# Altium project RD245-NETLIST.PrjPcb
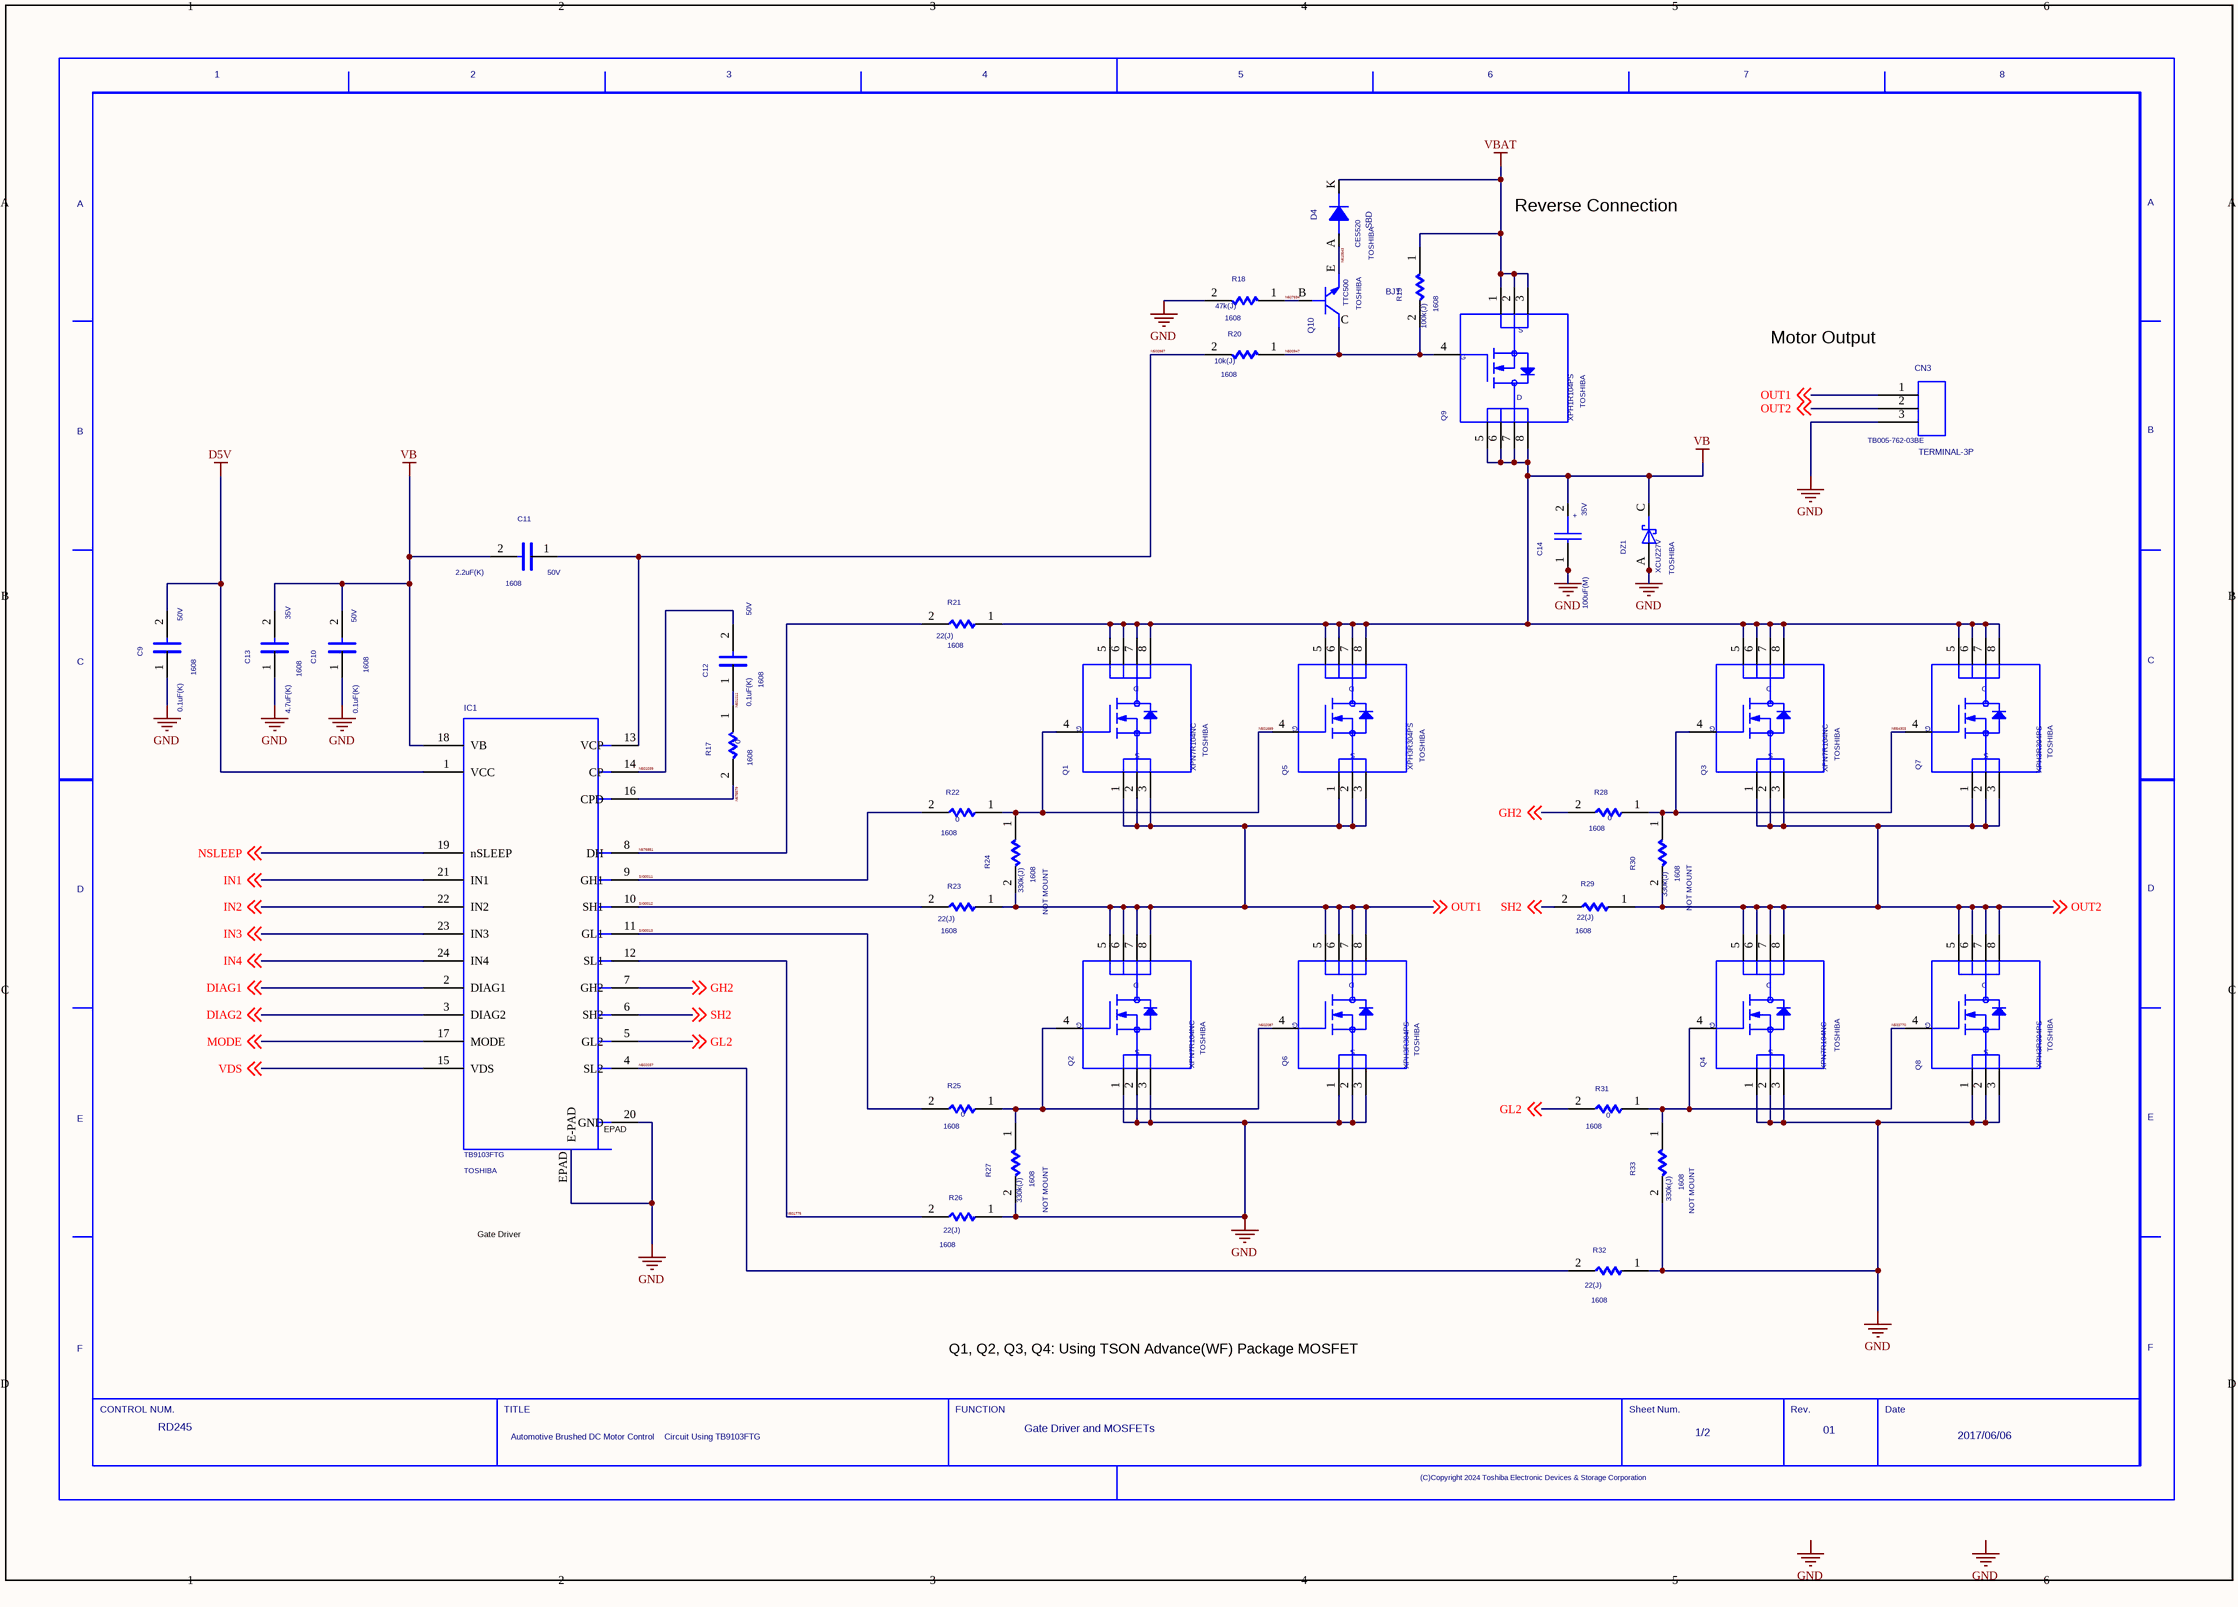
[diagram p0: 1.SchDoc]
2 sheets, 97 parts. Net scope: global (net labels, ports and power ports of the same name join across sheets).
Sheets:
  1.SchDoc
  2.SchDoc

## Sheet 1.SchDoc
size 420 x 297 mm

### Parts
(Parts that share a designator on the sheet are numbered #1, #2 ... from top to bottom, then left to right.)
C9  SIZECODESMD: 1608  VAL2: 50V  VAL1: 0.1uF(K)  (hidden comment: C)
C10  SIZECODESMD: 1608  VAL2: 50V  VAL1: 0.1uF(K)  (hidden comment: C)
C11  SIZECODESMD: 1608  VAL2: 50V  VAL1: 2.2uF(K)  (hidden comment: C)
C12  SIZECODESMD: 1608  VAL2: 50V  VAL1: 0.1uF(K)  (hidden comment: C)
C13  SIZECODESMD: 1608  VAL2: 35V  VAL1: 4.7uF(K)  (hidden comment: C)
C14  VAL2: 35V  VAL1: 100uF(M)  (hidden comment: CP)
CN3  TERMINAL-3P  VAL3: TB005-762-03BE
D4  SBD  USERCOMPTEXT3: TOSHIBA  VAL3: CES520
DZ1  VAL3: XCUZ27V  USERCOMPTEXT3: TOSHIBA  (hidden comment: SBD)
IC1  USERCOMPTEXT3: TOSHIBA  VAL3: TB9103FTG  (hidden comment: TC241_3)
Q1  VAL3: XPN7R104NC  USERCOMPTEXT3: TOSHIBA  (hidden comment: MFNAC)
Q2  VAL3: XPN7R104NC  USERCOMPTEXT3: TOSHIBA  (hidden comment: MFNAC)
Q3  VAL3: XPN7R104NC  USERCOMPTEXT3: TOSHIBA  (hidden comment: MFNAC)
Q4  VAL3: XPN7R104NC  USERCOMPTEXT3: TOSHIBA  (hidden comment: MFNAC)
Q5  VAL3: XPH3R304PS  USERCOMPTEXT3: TOSHIBA  (hidden comment: MFNAC)
Q6  VAL3: XPH3R304PS  USERCOMPTEXT3: TOSHIBA  (hidden comment: MFNAC)
Q7  VAL3: XPH3R304PS  USERCOMPTEXT3: TOSHIBA  (hidden comment: MFNAC)
Q8  VAL3: XPH3R304PS  USERCOMPTEXT3: TOSHIBA  (hidden comment: MFNAC)
Q9  VAL3: XPH1R104PS  USERCOMPTEXT3: TOSHIBA  (hidden comment: MFNAC)
Q10  BJT  USERCOMPTEXT3: TOSHIBA  VAL3: TTC500
R17  SIZECODESMD: 1608  VAL1: 0  (hidden comment: R)
R18  SIZECODESMD: 1608  VAL1: 47k(J)  (hidden comment: R)
R19  SIZECODESMD: 1608  VAL1: 100k(J)  (hidden comment: R)
R20  SIZECODESMD: 1608  VAL1: 10k(J)  (hidden comment: R)
R21  SIZECODESMD: 1608  VAL1: 22(J)  (hidden comment: R)
R22  SIZECODESMD: 1608  VAL1: 0  (hidden comment: R)
R23  SIZECODESMD: 1608  VAL1: 22(J)  (hidden comment: R)
R24  SIZECODESMD: 1608  VAL1: 330k(J)  NOTMOUNT: NOT MOUNT  (hidden comment: R)
R25  SIZECODESMD: 1608  VAL1: 0  (hidden comment: R)
R26  SIZECODESMD: 1608  VAL1: 22(J)  (hidden comment: R)
R27  SIZECODESMD: 1608  VAL1: 330k(J)  NOTMOUNT: NOT MOUNT  (hidden comment: R)
R28  SIZECODESMD: 1608  VAL1: 0  (hidden comment: R)
R29  SIZECODESMD: 1608  VAL1: 22(J)  (hidden comment: R)
R30  SIZECODESMD: 1608  VAL1: 330k(J)  NOTMOUNT: NOT MOUNT  (hidden comment: R)
R31  SIZECODESMD: 1608  VAL1: 0  (hidden comment: R)
R32  SIZECODESMD: 1608  VAL1: 22(J)  (hidden comment: R)
R33  SIZECODESMD: 1608  VAL1: 330k(J)  NOTMOUNT: NOT MOUNT  (hidden comment: R)
U?#1  DATE: 2017/06/06  REVISION: 01  FUNCTION: Gate Driver and MOSFETs  DRAWINGNUMBER: RD245  TITLE: Automotive Brushed DC Motor Control / Circuit Using TB9103FTG  SHEETNUMBER: 1/2  (hidden comment: WAKU_DEF100)

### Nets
D5V: C9.2 IC1.1(VCC)
GND: C9.1 C10.1 C13.1 C14.1 CN3.3 DZ1.A IC1.20(GND) IC1.EPAD(E-PAD) Q2.1 Q2.2 Q2.3 Q4.1 Q4.2 Q4.3 Q6.1 Q6.2 Q6.3 Q8.1 Q8.2 Q8.3 R18.2 R26.1 R27.2 R32.1 R33.2
VB: C10.2 C11.2 C13.2 C14.2 DZ1.C IC1.18(VB) Q1.5 Q1.6 Q1.7 Q1.8 Q3.5 Q3.6 Q3.7 Q3.8 Q5.5 Q5.6 Q5.7 Q5.8 Q7.5 Q7.6 Q7.7 Q7.8 Q9.5 Q9.6 Q9.7 Q9.8 R21.1
VBAT: D4.K Q9.1 Q9.2 Q9.3 R19.1
DIAG1: IC1.2(DIAG1) ; off-sheet DIAG1
DIAG2: IC1.3(DIAG2) ; off-sheet DIAG2
GH2: IC1.7(GH2) R28.2 ; off-sheet GH2
GL2: IC1.5(GL2) R31.2 ; off-sheet GL2
IN1: IC1.21(IN1) ; off-sheet IN1
IN2: IC1.22(IN2) ; off-sheet IN2
IN3: IC1.23(IN3) ; off-sheet IN3
IN4: IC1.24(IN4) ; off-sheet IN4
MODE: IC1.17(MODE) ; off-sheet MODE
N500947: Q9.4 Q10.C R19.2 R20.1
N500987: C11.1 IC1.13(VCP) R20.2
N501039: C12.2 IC1.14(CP)
N501211: C12.1 R17.1
N501689: Q1.4 Q5.4 R22.1 R24.1
N501775: IC1.12(SL1) R26.2
N502037: IC1.4(SL2) R32.2
N502087: Q2.4 Q6.4 R25.1 R27.1
N533770: Q4.4 Q8.4 R31.1 R33.1
N554303: Q3.4 Q7.4 R28.1 R30.1
N575579: IC1.16(CPD) R17.2
N576851: IC1.8(DH) R21.2
N607694: Q10.B R18.1
N610543: D4.A Q10.E
NSLEEP: IC1.19(nSLEEP) ; off-sheet NSLEEP
OUT1: CN3.1 Q1.1 Q1.2 Q1.3 Q2.5 Q2.6 Q2.7 Q2.8 Q5.1 Q5.2 Q5.3 Q6.5 Q6.6 Q6.7 Q6.8 R23.1 R24.2 ; off-sheet OUT1
OUT2: CN3.2 Q3.1 Q3.2 Q3.3 Q4.5 Q4.6 Q4.7 Q4.8 Q7.1 Q7.2 Q7.3 Q8.5 Q8.6 Q8.7 Q8.8 R29.1 R30.2 ; off-sheet OUT2
SH2: IC1.6(SH2) R29.2 ; off-sheet SH2
SIG0011: IC1.9(GH1) R22.2
SIG0012: IC1.10(SH1) R23.2
SIG0013: IC1.11(GL1) R25.2
VDS: IC1.15(VDS) ; off-sheet VDS

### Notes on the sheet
- Reverse Connection
  Protector
- Motor Output
- (near IC1) EPAD
- Gate Driver
- Q1, Q2, Q3, Q4: Using TSON Advance(WF) Package MOSFET
  Q5, Q6, Q7, Q8: Using SOP Advance(WF) Package MOSFET
- Labels drawn without touching a wire or pin: GND

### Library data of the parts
C9 = C: UPDATETIME: 17:22:43; UPDATEUSER: sptcae13; SAVECOUNT: 1; ORIGINALSYMBOLORIGIN: (0,0); QUADMODEL: CON_10U; FUNCN: C_C; NOMINALCAPACITA: 10u; RATEDVOLTAGE: 25; CDMASTERCADCELG: KC0167; MAKER: TDK; OUMEMAKER: MRT 村田製作所; ADSMODELNAME: s_ZRB18AR61E106ME01L; VAL4: Murata; FNLEADFREETHET1GT2GMCTH1: N_N_N; VAL3: GCM188R71H104KA57J; CAPACITANCETOLE: M; OUMECLASSIFICATION: セラミックコンデンサ; OUMEMAKERKATAMEI: ZRB18AR61E106ME01L; INSTANCENAME: INS530329
C10 = C: UPDATETIME: 17:22:43; UPDATEUSER: sptcae13; SAVECOUNT: 1; ORIGINALSYMBOLORIGIN: (0,0); QUADMODEL: CON_10U; FUNCN: C_C; NOMINALCAPACITA: 10u; RATEDVOLTAGE: 25; CDMASTERCADCELG: KC0167; MAKER: TDK; OUMEMAKER: MRT 村田製作所; ADSMODELNAME: s_ZRB18AR61E106ME01L; VAL4: Murata; FNLEADFREETHET1GT2GMCTH1: N_N_N; VAL3: GCM188R71H104KA57J; CAPACITANCETOLE: M; OUMECLASSIFICATION: セラミックコンデンサ; OUMEMAKERKATAMEI: ZRB18AR61E106ME01L; INSTANCENAME: INS530425
C11 = C: UPDATETIME: 17:22:43; UPDATEUSER: sptcae13; SAVECOUNT: 1; ORIGINALSYMBOLORIGIN: (0,0); QUADMODEL: CON_10U; FUNCN: C_C; NOMINALCAPACITA: 10u; RATEDVOLTAGE: 25; CDMASTERCADCELG: KC0167; MAKER: TDK; OUMEMAKER: MRT 村田製作所; ADSMODELNAME: s_ZRB18AR61E106ME01L; VAL4: Murata; FNLEADFREETHET1GT2GMCTH1: N_N_N; VAL3: GRT188R61H225KE13D; CAPACITANCETOLE: M; OUMECLASSIFICATION: セラミックコンデンサ; OUMEMAKERKATAMEI: ZRB18AR61E106ME01L; INSTANCENAME: INS530173
C12 = C: UPDATETIME: 17:22:43; UPDATEUSER: sptcae13; SAVECOUNT: 1; ORIGINALSYMBOLORIGIN: (0,0); QUADMODEL: CON_10U; FUNCN: C_C; NOMINALCAPACITA: 10u; RATEDVOLTAGE: 25; CDMASTERCADCELG: KC0167; MAKER: TDK; OUMEMAKER: MRT 村田製作所; ADSMODELNAME: s_ZRB18AR61E106ME01L; VAL4: Murata; FNLEADFREETHET1GT2GMCTH1: N_N_N; VAL3: GCM188R71H104KA57J; CAPACITANCETOLE: M; OUMECLASSIFICATION: セラミックコンデンサ; OUMEMAKERKATAMEI: ZRB18AR61E106ME01L; INSTANCENAME: INS529943
C13 = C: UPDATETIME: 17:22:43; UPDATEUSER: sptcae13; SAVECOUNT: 1; ORIGINALSYMBOLORIGIN: (0,0); QUADMODEL: CON_10U; FUNCN: C_C; NOMINALCAPACITA: 10u; RATEDVOLTAGE: 25; CDMASTERCADCELG: KC0167; MAKER: TDK; OUMEMAKER: MRT 村田製作所; ADSMODELNAME: s_ZRB18AR61E106ME01L; VAL4: Murata; FNLEADFREETHET1GT2GMCTH1: N_N_N; VAL3: GRT188R6YA475KE13D; CAPACITANCETOLE: M; OUMECLASSIFICATION: セラミックコンデンサ; OUMEMAKERKATAMEI: ZRB18AR61E106ME01L; INSTANCENAME: INS647841
C14 = CP: OUMEPARTTYPE: C; SAVEAREA0: -1450,-153,20294,13055; UPDATETIME: 16:13:42; UPDATEUSER: fukuda-y; TIME: 15:02:55; SAVECOUNT: 52; ORIGINALSYMBOLORIGIN: (0,0); QUADMODEL: CON_330U; FUNCN: CP_CP; RATEDVOLTAGE: 450; NOMINALCAPACITA: 330u; CDMASTERCADCELG: DC213N; MAKER: RUBYCON; GCOUNT: 1; SIZECODESMD: DIP; OUMEMAKER: SIT ルビコン; VAL4: Chemi-Con; FNLEADFREETHET1GT2GMCTH1: 9_N_N; VAL3: HHXD350ARA101MHA0G; CAPACITANCETOLE: M; OUMECLASSIFICATION: アルミ電解コンデンサ; OUMEMAKERKATAMEI: 450MXC330M35X40; CHIPSIZE: D35xL30; INSTANCENAME: INS636800
CN3 = CON3: SAVECOUNT: 1; UPDATEUSER: sptcae13; UPDATETIME: 09:49:24; OriginalSymbolOrigin: (0,0); FUNCN: CON3_CON3; VAL4: CUI Devices; VAL2: 300V/30A; INSTANCENAME: INS530345
D4 = DIODE_0: SAVECOUNT: 1; UPDATEUSER: sptcae13; UPDATETIME: 09:49:24; OriginalSymbolOrigin: (0,0); FUNCN: DIODE_0_DIODE_0; INSTANCENAME: INS530245
DZ1 = SBD: SAVEAREA0: -4630,-153,17114,13055; UPDATETIME: 08:16:22; UPDATEUSER: fukuda-y; TIME: 14:49:55; SAVECOUNT: 1; ORIGINALSYMBOLORIGIN: (0,0); COMPONENTNAME: SBD_SBD; INSTANCENAME: INS530189
IC1 = TC241_3: SAVECOUNT: 1; UPDATEUSER: sptcae13; UPDATETIME: 09:49:24; OriginalSymbolOrigin: (0,0); FUNCN: TC241_3_Graphic_Schematic_1_package; VAL1: GATE_DRIVER; INSTANCENAME: cmp65
Q1 = MFNAC_23: SAVEAREA0: -10143,-336,37609,28718; UPDATETIME: 14:45:16; UPDATEUSER: 19990028; TIME: 18:29:30; SAVECOUNT: 1; ORIGINALSYMBOLORIGIN: (0,0); COMPONENTNAME: MFNAC_23_MFNAC_23; INSTANCENAME: INS529903
Q2 = MFNAC_23: SAVEAREA0: -10143,-336,37609,28718; UPDATETIME: 14:45:16; UPDATEUSER: 19990028; TIME: 18:29:30; SAVECOUNT: 1; ORIGINALSYMBOLORIGIN: (0,0); COMPONENTNAME: MFNAC_23_MFNAC_23; INSTANCENAME: INS530205
Q3 = MFNAC_23: SAVEAREA0: -10143,-336,37609,28718; UPDATETIME: 14:45:16; UPDATEUSER: 19990028; TIME: 18:29:30; SAVECOUNT: 1; ORIGINALSYMBOLORIGIN: (0,0); COMPONENTNAME: MFNAC_23_MFNAC_23; INSTANCENAME: INS533486
Q4 = MFNAC_23: SAVEAREA0: -10143,-336,37609,28718; UPDATETIME: 14:45:16; UPDATEUSER: 19990028; TIME: 18:29:30; SAVECOUNT: 1; ORIGINALSYMBOLORIGIN: (0,0); COMPONENTNAME: MFNAC_23_MFNAC_23; INSTANCENAME: INS533696
Q5 = MFNAC_23: SAVEAREA0: -10143,-336,37609,28718; UPDATETIME: 14:45:16; UPDATEUSER: 19990028; TIME: 18:29:30; SAVECOUNT: 1; ORIGINALSYMBOLORIGIN: (0,0); COMPONENTNAME: MFNAC_23_MFNAC_23; INSTANCENAME: INS530025
Q6 = MFNAC_23: SAVEAREA0: -10143,-336,37609,28718; UPDATETIME: 14:45:16; UPDATEUSER: 19990028; TIME: 18:29:30; SAVECOUNT: 1; ORIGINALSYMBOLORIGIN: (0,0); COMPONENTNAME: MFNAC_23_MFNAC_23; INSTANCENAME: INS530385
Q7 = MFNAC_23: SAVEAREA0: -10143,-336,37609,28718; UPDATETIME: 14:45:16; UPDATEUSER: 19990028; TIME: 18:29:30; SAVECOUNT: 1; ORIGINALSYMBOLORIGIN: (0,0); COMPONENTNAME: MFNAC_23_MFNAC_23; INSTANCENAME: INS533510
Q8 = MFNAC_23: SAVEAREA0: -10143,-336,37609,28718; UPDATETIME: 14:45:16; UPDATEUSER: 19990028; TIME: 18:29:30; SAVECOUNT: 1; ORIGINALSYMBOLORIGIN: (0,0); COMPONENTNAME: MFNAC_23_MFNAC_23; INSTANCENAME: INS533720
Q9 = MFNAC_23: SAVEAREA0: -10143,-336,37609,28718; UPDATETIME: 14:45:16; UPDATEUSER: 19990028; TIME: 18:29:30; SAVECOUNT: 1; ORIGINALSYMBOLORIGIN: (0,0); COMPONENTNAME: MFNAC_23_MFNAC_23; INSTANCENAME: INS529983
Q10 = 2N1069_0: SAVECOUNT: 1; UPDATEUSER: sptcae13; UPDATETIME: 09:49:24; PSPICETEMPLATE: Q^@REFDES %C %B %E; OriginalSymbolOrigin: (0,5080); FUNCN: 2N1069_0_2N1069_0; INSTANCENAME: INS529959
R17 = R: UPDATETIME: 17:22:43; UPDATEUSER: sptcae13; SAVECOUNT: 1; ORIGINALSYMBOLORIGIN: (0,0); QUADMODEL: RES_1M; FUNCN: R_R; CDMASTERCADCELG: KC0020; MAKER: KOA; RESISTANCETOLER: J; OUMEMAKER: SSM 進工業; POWERRATING: 500m; MOUNTINGFORMSMD: SMD; NOMINALRESISTAN: 1m; ADSMODELNAME: s_RL1632H_R001_JN; FNLEADFREETHET1GT2GMCTH1: N_N_N; VAL3: RK73Z1JTTD; OUMECLASSIFICATION: 表面実装用固定抵抗器; OUMEMAKERKATAMEI: RL1632H-R001-JN; CHIPSIZE: 3216; INSTANCENAME: INS529855
R18 = R: UPDATETIME: 17:22:43; UPDATEUSER: sptcae13; SAVECOUNT: 1; ORIGINALSYMBOLORIGIN: (0,0); QUADMODEL: RES_1M; FUNCN: R_R; CDMASTERCADCELG: KC0020; MAKER: KOA; RESISTANCETOLER: J; OUMEMAKER: SSM 進工業; POWERRATING: 500m; MOUNTINGFORMSMD: SMD; NOMINALRESISTAN: 1m; ADSMODELNAME: s_RL1632H_R001_JN; FNLEADFREETHET1GT2GMCTH1: N_N_N; VAL3: RK73B1JTTD473J; VAL2: 100mW; OUMECLASSIFICATION: 表面実装用固定抵抗器; OUMEMAKERKATAMEI: RL1632H-R001-JN; CHIPSIZE: 3216; INSTANCENAME: INS529871
R19 = R: UPDATETIME: 17:22:43; UPDATEUSER: sptcae13; SAVECOUNT: 1; ORIGINALSYMBOLORIGIN: (0,0); QUADMODEL: RES_1M; FUNCN: R_R; CDMASTERCADCELG: KC0020; MAKER: KOA; RESISTANCETOLER: J; OUMEMAKER: SSM 進工業; POWERRATING: 500m; MOUNTINGFORMSMD: SMD; NOMINALRESISTAN: 1m; ADSMODELNAME: s_RL1632H_R001_JN; FNLEADFREETHET1GT2GMCTH1: N_N_N; VAL3: RK73B1JTTD104J; VAL2: 100mW; OUMECLASSIFICATION: 表面実装用固定抵抗器; OUMEMAKERKATAMEI: RL1632H-R001-JN; CHIPSIZE: 3216; INSTANCENAME: INS530265
R20 = R: UPDATETIME: 17:22:43; UPDATEUSER: sptcae13; SAVECOUNT: 1; ORIGINALSYMBOLORIGIN: (0,0); QUADMODEL: RES_1M; FUNCN: R_R; CDMASTERCADCELG: KC0020; MAKER: KOA; RESISTANCETOLER: J; OUMEMAKER: SSM 進工業; POWERRATING: 500m; MOUNTINGFORMSMD: SMD; NOMINALRESISTAN: 1m; ADSMODELNAME: s_RL1632H_R001_JN; FNLEADFREETHET1GT2GMCTH1: N_N_N; VAL3: RK73B1JTTD103J; VAL2: 100mW; OUMECLASSIFICATION: 表面実装用固定抵抗器; OUMEMAKERKATAMEI: RL1632H-R001-JN; CHIPSIZE: 3216; INSTANCENAME: INS529887
R21 = R: UPDATETIME: 17:22:43; UPDATEUSER: sptcae13; SAVECOUNT: 1; ORIGINALSYMBOLORIGIN: (0,0); QUADMODEL: RES_1M; FUNCN: R_R; CDMASTERCADCELG: KC0020; MAKER: KOA; RESISTANCETOLER: J; OUMEMAKER: SSM 進工業; POWERRATING: 500m; MOUNTINGFORMSMD: SMD; NOMINALRESISTAN: 1m; ADSMODELNAME: s_RL1632H_R001_JN; FNLEADFREETHET1GT2GMCTH1: N_N_N; VAL3: RK73B1JTTD220J; VAL2: 125mW; OUMECLASSIFICATION: 表面実装用固定抵抗器; OUMEMAKERKATAMEI: RL1632H-R001-JN; CHIPSIZE: 3216; INSTANCENAME: INS575614
R22 = R: UPDATETIME: 17:22:43; UPDATEUSER: sptcae13; SAVECOUNT: 1; ORIGINALSYMBOLORIGIN: (0,0); QUADMODEL: RES_1M; FUNCN: R_R; CDMASTERCADCELG: KC0020; MAKER: KOA; RESISTANCETOLER: J; OUMEMAKER: SSM 進工業; POWERRATING: 500m; MOUNTINGFORMSMD: SMD; NOMINALRESISTAN: 1m; ADSMODELNAME: s_RL1632H_R001_JN; FNLEADFREETHET1GT2GMCTH1: N_N_N; VAL3: RK73Z1JTTD; OUMECLASSIFICATION: 表面実装用固定抵抗器; OUMEMAKERKATAMEI: RL1632H-R001-JN; CHIPSIZE: 3216; INSTANCENAME: INS530281
R23 = R: UPDATETIME: 17:22:43; UPDATEUSER: sptcae13; SAVECOUNT: 1; ORIGINALSYMBOLORIGIN: (0,0); QUADMODEL: RES_1M; FUNCN: R_R; CDMASTERCADCELG: KC0020; MAKER: KOA; RESISTANCETOLER: J; OUMEMAKER: SSM 進工業; POWERRATING: 500m; MOUNTINGFORMSMD: SMD; NOMINALRESISTAN: 1m; ADSMODELNAME: s_RL1632H_R001_JN; FNLEADFREETHET1GT2GMCTH1: N_N_N; VAL3: RK73B1JTTD220J; VAL2: 125mW; OUMECLASSIFICATION: 表面実装用固定抵抗器; OUMEMAKERKATAMEI: RL1632H-R001-JN; CHIPSIZE: 3216; INSTANCENAME: INS577102
R24 = R: UPDATETIME: 17:22:43; UPDATEUSER: sptcae13; SAVECOUNT: 1; ORIGINALSYMBOLORIGIN: (0,0); QUADMODEL: RES_1M; FUNCN: R_R; CDMASTERCADCELG: KC0020; MAKER: KOA; RESISTANCETOLER: J; OUMEMAKER: SSM 進工業; POWERRATING: 500m; MOUNTINGFORMSMD: SMD; NOMINALRESISTAN: 1m; ADSMODELNAME: s_RL1632H_R001_JN; FNLEADFREETHET1GT2GMCTH1: N_N_N; VAL3: RK73B1JTTD334J; VAL2: 100mW; OUMECLASSIFICATION: 表面実装用固定抵抗器; OUMEMAKERKATAMEI: RL1632H-R001-JN; CHIPSIZE: 3216; INSTANCENAME: INS586735
R25 = R: UPDATETIME: 17:22:43; UPDATEUSER: sptcae13; SAVECOUNT: 1; ORIGINALSYMBOLORIGIN: (0,0); QUADMODEL: RES_1M; FUNCN: R_R; CDMASTERCADCELG: KC0020; MAKER: KOA; RESISTANCETOLER: J; OUMEMAKER: SSM 進工業; POWERRATING: 500m; MOUNTINGFORMSMD: SMD; NOMINALRESISTAN: 1m; ADSMODELNAME: s_RL1632H_R001_JN; FNLEADFREETHET1GT2GMCTH1: N_N_N; VAL3: RK73Z1JTTD; OUMECLASSIFICATION: 表面実装用固定抵抗器; OUMEMAKERKATAMEI: RL1632H-R001-JN; CHIPSIZE: 3216; INSTANCENAME: INS530297
R26 = R: UPDATETIME: 17:22:43; UPDATEUSER: sptcae13; SAVECOUNT: 1; ORIGINALSYMBOLORIGIN: (0,0); QUADMODEL: RES_1M; FUNCN: R_R; CDMASTERCADCELG: KC0020; MAKER: KOA; RESISTANCETOLER: J; OUMEMAKER: SSM 進工業; POWERRATING: 500m; MOUNTINGFORMSMD: SMD; NOMINALRESISTAN: 1m; ADSMODELNAME: s_RL1632H_R001_JN; FNLEADFREETHET1GT2GMCTH1: N_N_N; VAL3: RK73B1JTTD220J; VAL2: 125mW; OUMECLASSIFICATION: 表面実装用固定抵抗器; OUMEMAKERKATAMEI: RL1632H-R001-JN; CHIPSIZE: 3216; INSTANCENAME: INS577602
R27 = R: UPDATETIME: 17:22:43; UPDATEUSER: sptcae13; SAVECOUNT: 1; ORIGINALSYMBOLORIGIN: (0,0); QUADMODEL: RES_1M; FUNCN: R_R; CDMASTERCADCELG: KC0020; MAKER: KOA; RESISTANCETOLER: J; OUMEMAKER: SSM 進工業; POWERRATING: 500m; MOUNTINGFORMSMD: SMD; NOMINALRESISTAN: 1m; ADSMODELNAME: s_RL1632H_R001_JN; FNLEADFREETHET1GT2GMCTH1: N_N_N; VAL3: RK73B1JTTD334J; VAL2: 100mW; OUMECLASSIFICATION: 表面実装用固定抵抗器; OUMEMAKERKATAMEI: RL1632H-R001-JN; CHIPSIZE: 3216; INSTANCENAME: INS591774
R28 = R: UPDATETIME: 17:22:43; UPDATEUSER: sptcae13; SAVECOUNT: 1; ORIGINALSYMBOLORIGIN: (0,0); QUADMODEL: RES_1M; FUNCN: R_R; CDMASTERCADCELG: KC0020; MAKER: KOA; RESISTANCETOLER: J; OUMEMAKER: SSM 進工業; POWERRATING: 500m; MOUNTINGFORMSMD: SMD; NOMINALRESISTAN: 1m; ADSMODELNAME: s_RL1632H_R001_JN; FNLEADFREETHET1GT2GMCTH1: N_N_N; VAL3: RK73Z1JTTD; OUMECLASSIFICATION: 表面実装用固定抵抗器; OUMEMAKERKATAMEI: RL1632H-R001-JN; CHIPSIZE: 3216; INSTANCENAME: INS533534
R29 = R: UPDATETIME: 17:22:43; UPDATEUSER: sptcae13; SAVECOUNT: 1; ORIGINALSYMBOLORIGIN: (0,0); QUADMODEL: RES_1M; FUNCN: R_R; CDMASTERCADCELG: KC0020; MAKER: KOA; RESISTANCETOLER: J; OUMEMAKER: SSM 進工業; POWERRATING: 500m; MOUNTINGFORMSMD: SMD; NOMINALRESISTAN: 1m; ADSMODELNAME: s_RL1632H_R001_JN; FNLEADFREETHET1GT2GMCTH1: N_N_N; VAL3: RK73B1JTTD220J; VAL2: 125mW; OUMECLASSIFICATION: 表面実装用固定抵抗器; OUMEMAKERKATAMEI: RL1632H-R001-JN; CHIPSIZE: 3216; INSTANCENAME: INS579870
R30 = R: UPDATETIME: 17:22:43; UPDATEUSER: sptcae13; SAVECOUNT: 1; ORIGINALSYMBOLORIGIN: (0,0); QUADMODEL: RES_1M; FUNCN: R_R; CDMASTERCADCELG: KC0020; MAKER: KOA; RESISTANCETOLER: J; OUMEMAKER: SSM 進工業; POWERRATING: 500m; MOUNTINGFORMSMD: SMD; NOMINALRESISTAN: 1m; ADSMODELNAME: s_RL1632H_R001_JN; FNLEADFREETHET1GT2GMCTH1: N_N_N; VAL3: RK73B1JTTD334J; VAL2: 100mW; OUMECLASSIFICATION: 表面実装用固定抵抗器; OUMEMAKERKATAMEI: RL1632H-R001-JN; CHIPSIZE: 3216; INSTANCENAME: INS592756
R31 = R: UPDATETIME: 17:22:43; UPDATEUSER: sptcae13; SAVECOUNT: 1; ORIGINALSYMBOLORIGIN: (0,0); QUADMODEL: RES_1M; FUNCN: R_R; CDMASTERCADCELG: KC0020; MAKER: KOA; RESISTANCETOLER: J; OUMEMAKER: SSM 進工業; POWERRATING: 500m; MOUNTINGFORMSMD: SMD; NOMINALRESISTAN: 1m; ADSMODELNAME: s_RL1632H_R001_JN; FNLEADFREETHET1GT2GMCTH1: N_N_N; VAL3: RK73Z1JTTD; OUMECLASSIFICATION: 表面実装用固定抵抗器; OUMEMAKERKATAMEI: RL1632H-R001-JN; CHIPSIZE: 3216; INSTANCENAME: INS533744
R32 = R: UPDATETIME: 17:22:43; UPDATEUSER: sptcae13; SAVECOUNT: 1; ORIGINALSYMBOLORIGIN: (0,0); QUADMODEL: RES_1M; FUNCN: R_R; CDMASTERCADCELG: KC0020; MAKER: KOA; RESISTANCETOLER: J; OUMEMAKER: SSM 進工業; POWERRATING: 500m; MOUNTINGFORMSMD: SMD; NOMINALRESISTAN: 1m; ADSMODELNAME: s_RL1632H_R001_JN; FNLEADFREETHET1GT2GMCTH1: N_N_N; VAL3: RK73B1JTTD220J; VAL2: 125mW; OUMECLASSIFICATION: 表面実装用固定抵抗器; OUMEMAKERKATAMEI: RL1632H-R001-JN; CHIPSIZE: 3216; INSTANCENAME: INS577624
R33 = R: UPDATETIME: 17:22:43; UPDATEUSER: sptcae13; SAVECOUNT: 1; ORIGINALSYMBOLORIGIN: (0,0); QUADMODEL: RES_1M; FUNCN: R_R; CDMASTERCADCELG: KC0020; MAKER: KOA; RESISTANCETOLER: J; OUMEMAKER: SSM 進工業; POWERRATING: 500m; MOUNTINGFORMSMD: SMD; NOMINALRESISTAN: 1m; ADSMODELNAME: s_RL1632H_R001_JN; FNLEADFREETHET1GT2GMCTH1: N_N_N; VAL3: RK73B1JTTD334J; VAL2: 100mW; OUMECLASSIFICATION: 表面実装用固定抵抗器; OUMEMAKERKATAMEI: RL1632H-R001-JN; CHIPSIZE: 3216; INSTANCENAME: INS592511
U?#1 = WAKU_DEF100_1: SAVECOUNT: 1; UPDATEUSER: sptcae09; UPDATETIME: 10:40:02; PLOTTIME: HH:MM; TIME: 09:49:24; SAVEAREA0: -63393,-16950,474261,314592; ORIGINALSYMBOLORIGIN: (0,0); PAGENUMBER: 8; DESIGNED: TOSHIBA; SHTSAVECOUNT: 37; INSTANCENAME: INS636826

## Sheet 2.SchDoc
size 420 x 297 mm
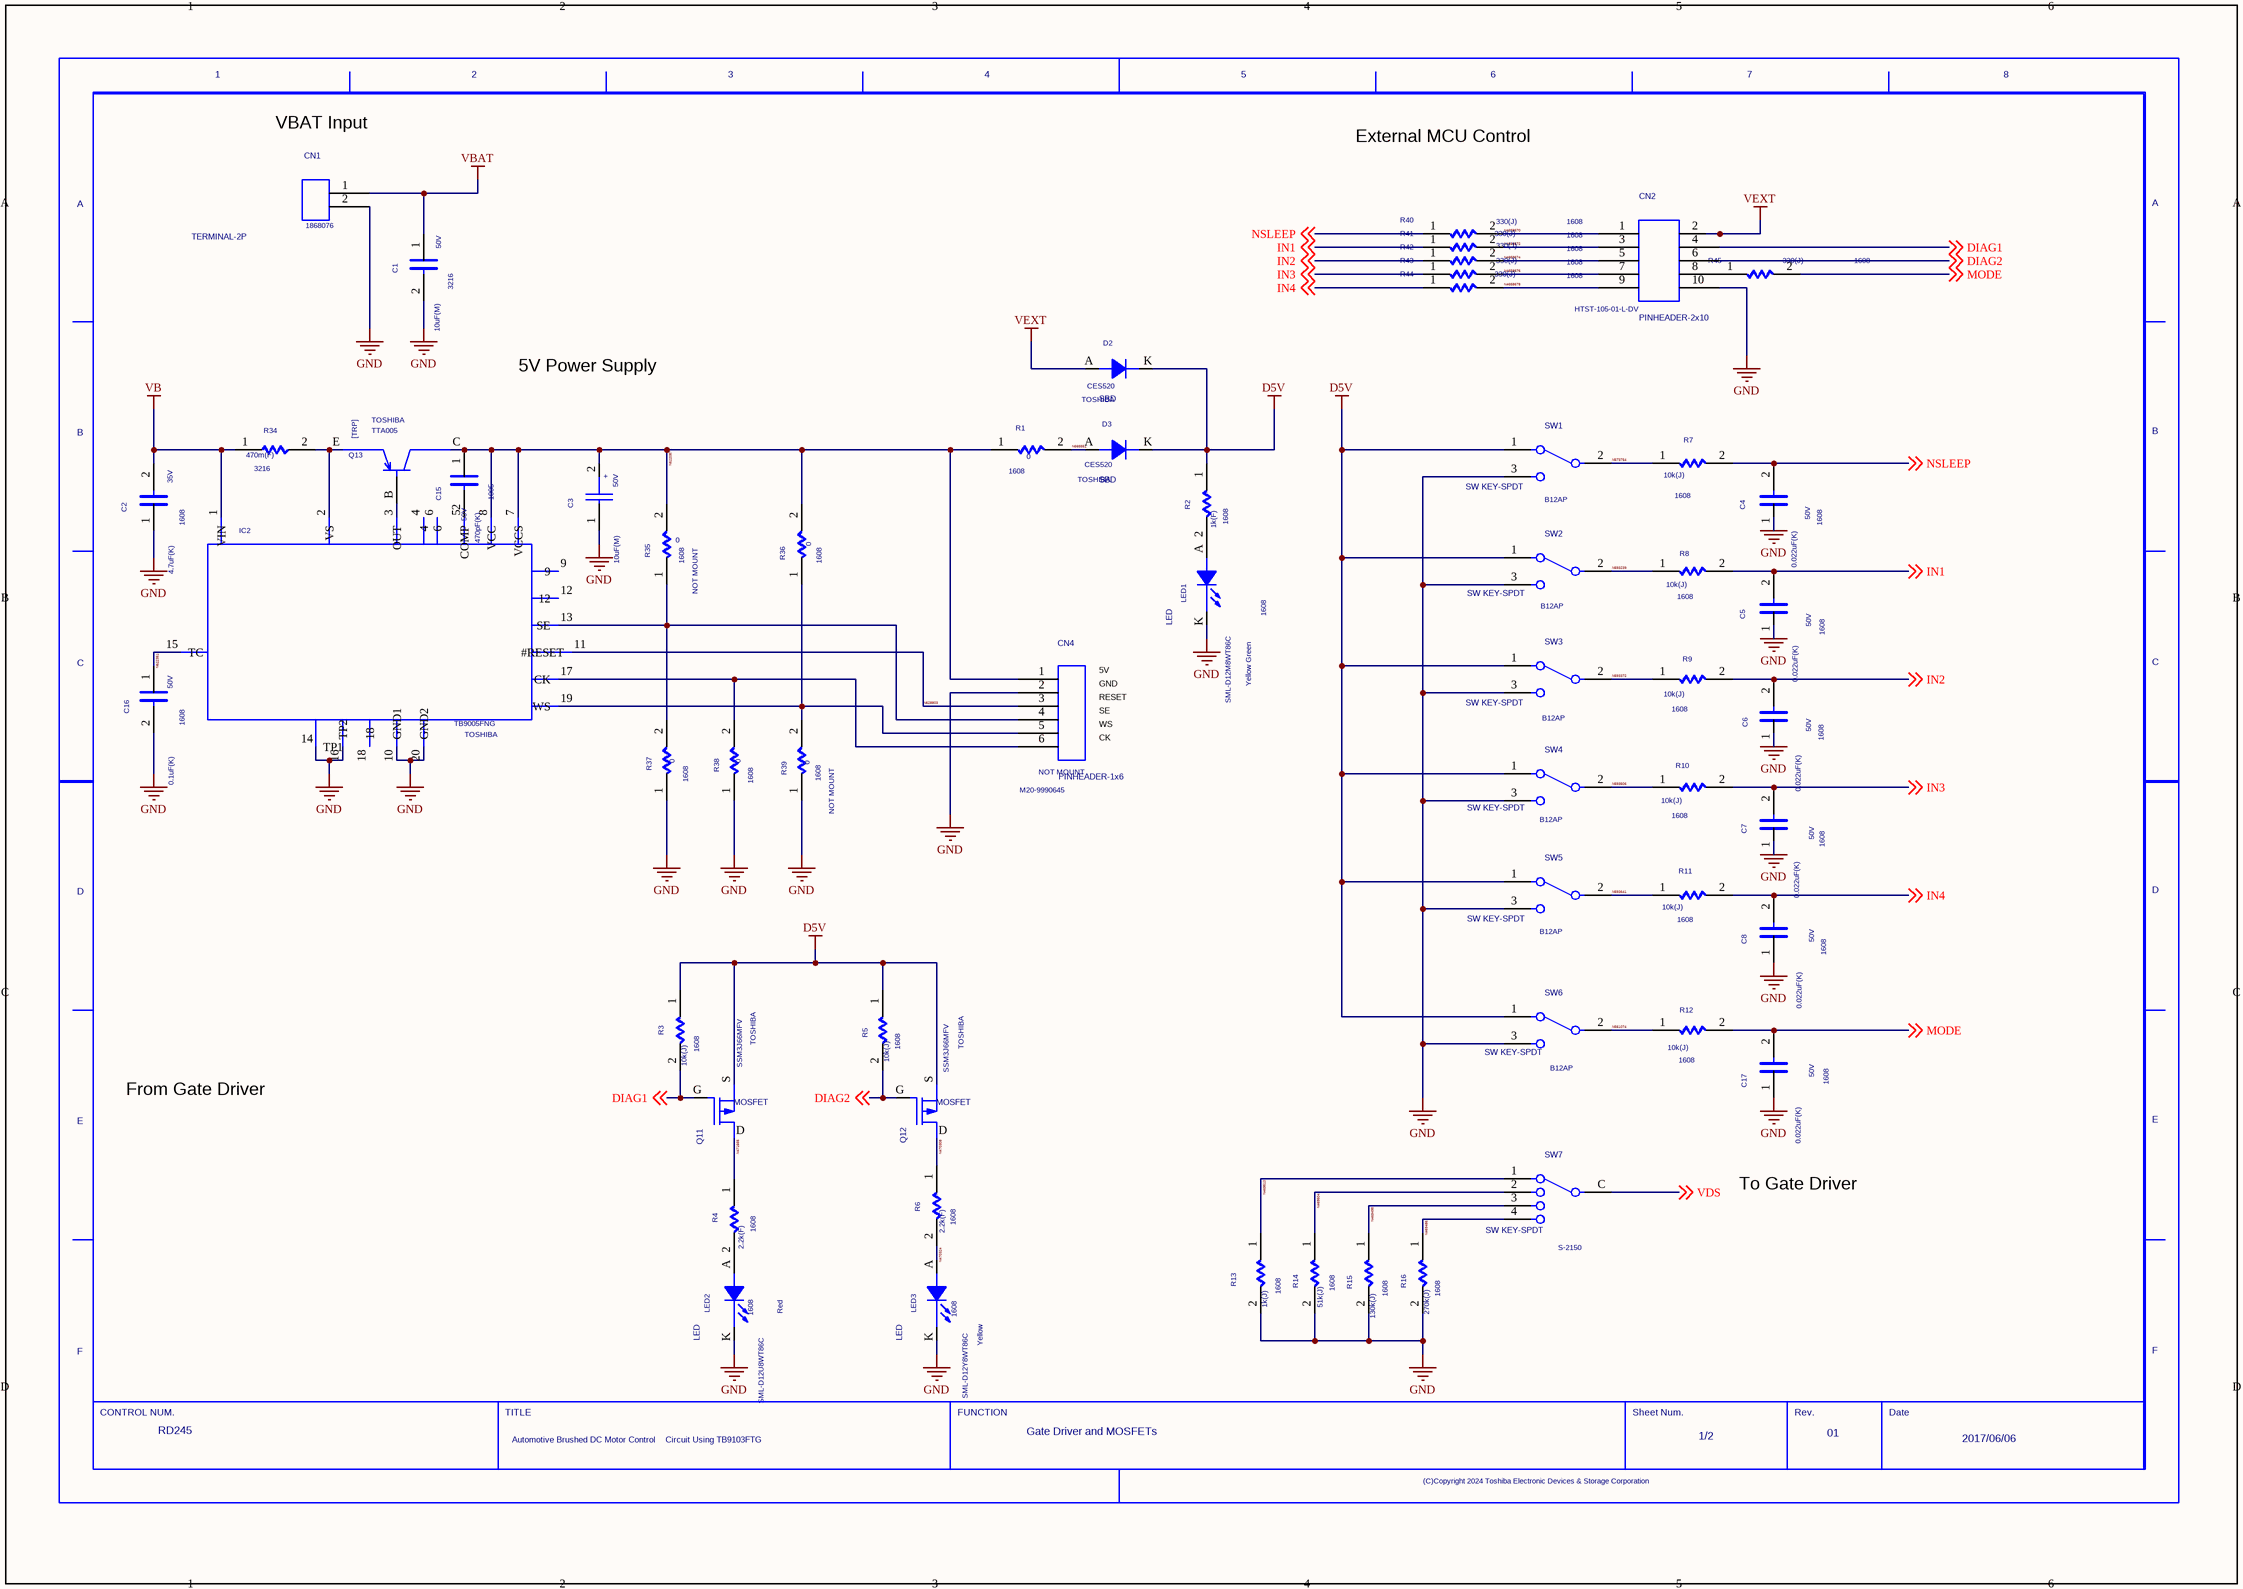
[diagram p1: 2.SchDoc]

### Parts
(Parts that share a designator on the sheet are numbered #1, #2 ... from top to bottom, then left to right.)
C1  SIZECODESMD: 3216  VAL2: 50V  VAL1: 10uF(M)  (hidden comment: C)
C2  SIZECODESMD: 1608  VAL2: 35V  VAL1: 4.7uF(K)  (hidden comment: C)
C3  VAL2: 50V  VAL1: 10uF(M)  (hidden comment: CP)
C4  SIZECODESMD: 1608  VAL2: 50V  VAL1: 0.022uF(K)  (hidden comment: C)
C5  SIZECODESMD: 1608  VAL2: 50V  VAL1: 0.022uF(K)  (hidden comment: C)
C6  SIZECODESMD: 1608  VAL2: 50V  VAL1: 0.022uF(K)  (hidden comment: C)
C7  SIZECODESMD: 1608  VAL2: 50V  VAL1: 0.022uF(K)  (hidden comment: C)
C8  SIZECODESMD: 1608  VAL2: 50V  VAL1: 0.022uF(K)  (hidden comment: C)
C15  SIZECODESMD: 1005  VAL2: 50V  VAL1: 470pF(K)  (hidden comment: C)
C16  SIZECODESMD: 1608  VAL2: 50V  VAL1: 0.1uF(K)  (hidden comment: C)
C17  SIZECODESMD: 1608  VAL2: 50V  VAL1: 0.022uF(K)  (hidden comment: C)
CN1  TERMINAL-2P  VAL3: 1868076
CN2  PINHEADER-2x10  VAL3: HTST-105-01-L-DV
CN4  PINHEADER-1x6  NOTMOUNT: NOT MOUNT  VAL3: M20-9990645
D2  SBD  USERCOMPTEXT3: TOSHIBA  VAL3: CES520
D3  SBD  USERCOMPTEXT3: TOSHIBA  VAL3: CES520
IC2  USERCOMPTEXT3: TOSHIBA  (hidden comment: TB9005FNG)
LED1  LED  SIZECODESMD: 1608  VAL3: SML-D12M8WT86C  VAL1: Yellow Green
LED2  LED  SIZECODESMD: 1608  VAL3: SML-D12U8WT86C  VAL1: Red
LED3  LED  SIZECODESMD: 1608  VAL3: SML-D12Y8WT86C  VAL1: Yellow
Q11  MOSFET  USERCOMPTEXT3: TOSHIBA  VAL3: SSM3J66MFV
Q12  MOSFET  USERCOMPTEXT3: TOSHIBA  VAL3: SSM3J66MFV
Q13  USERCOMPTEXT3: TOSHIBA  VAL3: TTA005  (hidden comment: TRP)
R1  SIZECODESMD: 1608  VAL1: 0  (hidden comment: R)
R2  SIZECODESMD: 1608  VAL1: 1k(F)  (hidden comment: R)
R3  SIZECODESMD: 1608  VAL1: 10k(J)  (hidden comment: R)
R4  SIZECODESMD: 1608  VAL1: 2.2k(F)  (hidden comment: R)
R5  SIZECODESMD: 1608  VAL1: 10k(J)  (hidden comment: R)
R6  SIZECODESMD: 1608  VAL1: 2.2k(F)  (hidden comment: R)
R7  SIZECODESMD: 1608  VAL1: 10k(J)  (hidden comment: R)
R8  SIZECODESMD: 1608  VAL1: 10k(J)  (hidden comment: R)
R9  SIZECODESMD: 1608  VAL1: 10k(J)  (hidden comment: R)
R10  SIZECODESMD: 1608  VAL1: 10k(J)  (hidden comment: R)
R11  SIZECODESMD: 1608  VAL1: 10k(J)  (hidden comment: R)
R12  SIZECODESMD: 1608  VAL1: 10k(J)  (hidden comment: R)
R13  SIZECODESMD: 1608  VAL1: 1k(J)  (hidden comment: R)
R14  SIZECODESMD: 1608  VAL1: 51k(J)  (hidden comment: R)
R15  SIZECODESMD: 1608  VAL1: 130k(J)  (hidden comment: R)
R16  SIZECODESMD: 1608  VAL1: 270k(J)  (hidden comment: R)
R34  SIZECODESMD: 3216  VAL1: 470m(F)  (hidden comment: R)
R35  SIZECODESMD: 1608  VAL1: 0  NOTMOUNT: NOT MOUNT  (hidden comment: R)
R36  SIZECODESMD: 1608  VAL1: 0  (hidden comment: R)
R37  SIZECODESMD: 1608  VAL1: 0  (hidden comment: R)
R38  SIZECODESMD: 1608  VAL1: 0  (hidden comment: R)
R39  SIZECODESMD: 1608  VAL1: 0  NOTMOUNT: NOT MOUNT  (hidden comment: R)
R40  SIZECODESMD: 1608  VAL1: 330(J)  (hidden comment: R)
R41  SIZECODESMD: 1608  VAL1: 330(J)  (hidden comment: R)
R42  SIZECODESMD: 1608  VAL1: 330(J)  (hidden comment: R)
R43  SIZECODESMD: 1608  VAL1: 330(J)  (hidden comment: R)
R44  SIZECODESMD: 1608  VAL1: 330(J)  (hidden comment: R)
R45  SIZECODESMD: 1608  VAL1: 330(J)  (hidden comment: R)
SW1  SW KEY-SPDT  VAL3: B12AP
SW2  SW KEY-SPDT  VAL3: B12AP
SW3  SW KEY-SPDT  VAL3: B12AP
SW4  SW KEY-SPDT  VAL3: B12AP
SW5  SW KEY-SPDT  VAL3: B12AP
SW6  SW KEY-SPDT  VAL3: B12AP
SW7  SW KEY-SPDT  VAL3: S-2150
U?#2  DATE: 2017/06/06  REVISION: 01  FUNCTION: Gate Driver and MOSFETs  DRAWINGNUMBER: RD245  TITLE: Automotive Brushed DC Motor Control / Circuit Using TB9103FTG  SHEETNUMBER: 1/2  (hidden comment: WAKU_DEF100)

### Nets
D5V: D2.K D3.K Q11.S Q12.S R2.1 R3.1 R5.1 SW1.1(NC) SW2.1(NC) SW3.1(NC) SW4.1(NC) SW5.1(NC) SW6.1(NC)
GND: C1.2 C2.1 C3.1 C4.1 C5.1 C6.1 C7.1 C8.1 C16.2 C17.1 CN1.2 CN2.10 CN4.2 IC2.10(GND1) IC2.14(TP1) IC2.16(TP2) IC2.20(GND2) LED1.K LED2.K LED3.K R13.2 R14.2 R15.2 R16.2 R37.1 R38.1 R39.1 SW1.3(NO) SW2.3(NO) SW3.3(NO) SW4.3(NO) SW5.3(NO) SW6.3(NO)
VB: C2.2 IC2.1(VIN) R34.1
VBAT: C1.1 CN1.1
VEXT: CN2.2 D2.A
DIAG1: CN2.4 Q11.G R3.2 ; off-sheet DIAG1
DIAG2: CN2.6 Q12.G R5.2 ; off-sheet DIAG2
IN1: C5.2 R8.2 R41.1 ; off-sheet IN1
IN2: C6.2 R9.2 R42.1 ; off-sheet IN2
IN3: C7.2 R10.2 R43.1 ; off-sheet IN3
IN4: C8.2 R11.2 R44.1 ; off-sheet IN4
MODE: C17.2 R12.2 R45.2 ; off-sheet MODE
N469486: R16.1 SW7.4(NO)
N469495: R15.1 SW7.3(NO)
N469504: R14.1 SW7.2(COMMON)
N469513: R13.1 SW7.1(NC)
N470308: Q12.D R6.1
N470324: LED3.A R6.2
N471565: Q11.D R4.1
N561074: R12.1 SW6.2(COMMON)
N573754: R7.1 SW1.2(COMMON)
N593239: R8.1 SW2.2(COMMON)
N593372: R9.1 SW3.2(COMMON)
N593506: R10.1 SW4.2(COMMON)
N593641: R11.1 SW5.2(COMMON)
N622087: C3.2 C15.1 CN4.1 IC2.7(VCCS) IC2.8(VCC) Q13.C R1.1 R35.2 R36.2
N622351: C16.1 IC2.15(TC)
N628803: CN4.3 IC2.11(#RESET)
N665551: D3.A R1.2
N4658670: CN2.1 R40.2
N4658672: CN2.3 R41.2
N4658674: CN2.5 R42.2
N4658676: CN2.7 R43.2
N4658678: CN2.9 R44.2
NSLEEP: C4.2 R7.2 R40.1 ; off-sheet NSLEEP
SIG595: CN4.4 IC2.13(SE) R35.1 R37.2
SIG638: IC2.3(OUT) Q13.B
SIG639: IC2.2(VS) Q13.E R34.2
SIG642: CN4.5 IC2.19(WS) R36.1 R39.2
SIG643: CN4.6 IC2.17(CK) R38.2
VDS: SW7.C(NO) ; off-sheet VDS
NetC15_2: C15.2 IC2.5(COMP)
NetCN2_8: CN2.8 R45.1
NetLED1_A: LED1.A R2.2
NetLED2_A: LED2.A R4.2

Not connected (* = marked no-connect by the designer): IC2 4 6 9 12 18

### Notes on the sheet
- VBAT Input
- External MCU Control
- 5V Power Supply
- (near CN4) 5V
- (near CN4) GND
- (near CN4) RESET
- (near CN4) SE
- (near CN4) WS
- (near CN4) CK
- From Gate Driver
- To Gate Driver

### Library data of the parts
C1 = C: UPDATETIME: 17:22:43; UPDATEUSER: sptcae13; SAVECOUNT: 1; ORIGINALSYMBOLORIGIN: (0,0); FUNCN: C_C; VAL4: Murata; VAL3: GRT31CR61H106ME01L; CDBNAME: C0805K_2; INSTANCENAME: cmp141
C2 = C: UPDATETIME: 17:22:43; UPDATEUSER: sptcae13; SAVECOUNT: 1; ORIGINALSYMBOLORIGIN: (0,0); QUADMODEL: CON_10U; FUNCN: C_C; NOMINALCAPACITA: 10u; RATEDVOLTAGE: 25; CDMASTERCADCELG: KC0167; MAKER: TDK; OUMEMAKER: MRT 村田製作所; ADSMODELNAME: s_ZRB18AR61E106ME01L; VAL4: Murata; FNLEADFREETHET1GT2GMCTH1: N_N_N; VAL3: GRT188R6YA475KE13D; CAPACITANCETOLE: M; OUMECLASSIFICATION: セラミックコンデンサ; OUMEMAKERKATAMEI: ZRB18AR61E106ME01L; INSTANCENAME: INS669941
C3 = CP: OUMEPARTTYPE: C; SAVEAREA0: -1450,-153,20294,13055; UPDATETIME: 16:13:42; UPDATEUSER: fukuda-y; TIME: 15:02:55; SAVECOUNT: 52; ORIGINALSYMBOLORIGIN: (0,0); QUADMODEL: CON_330U; FUNCN: CP_CP; RATEDVOLTAGE: 450; NOMINALCAPACITA: 330u; CDMASTERCADCELG: DC213N; MAKER: RUBYCON; GCOUNT: 1; SIZECODESMD: DIP; OUMEMAKER: SIT ルビコン; VAL4: Chemi-Con; FNLEADFREETHET1GT2GMCTH1: 9_N_N; VAL3: HHXD500ARA100MF61G; CAPACITANCETOLE: M; OUMECLASSIFICATION: アルミ電解コンデンサ; OUMEMAKERKATAMEI: 450MXC330M35X40; CHIPSIZE: D35xL30; INSTANCENAME: INS634215
C4 = C: UPDATETIME: 17:22:43; UPDATEUSER: sptcae13; SAVECOUNT: 1; ORIGINALSYMBOLORIGIN: (0,0); QUADMODEL: CON_10U; FUNCN: C_C; NOMINALCAPACITA: 10u; RATEDVOLTAGE: 25; CDMASTERCADCELG: KC0167; MAKER: TDK; OUMEMAKER: MRT 村田製作所; ADSMODELNAME: s_ZRB18AR61E106ME01L; VAL4: Murata; FNLEADFREETHET1GT2GMCTH1: N_N_N; VAL3: GCM188R91H223KA37D; CAPACITANCETOLE: M; OUMECLASSIFICATION: セラミックコンデンサ; OUMEMAKERKATAMEI: ZRB18AR61E106ME01L; INSTANCENAME: INS573773
C5 = C: UPDATETIME: 17:22:43; UPDATEUSER: sptcae13; SAVECOUNT: 1; ORIGINALSYMBOLORIGIN: (0,0); QUADMODEL: CON_10U; FUNCN: C_C; NOMINALCAPACITA: 10u; RATEDVOLTAGE: 25; CDMASTERCADCELG: KC0167; MAKER: TDK; OUMEMAKER: MRT 村田製作所; ADSMODELNAME: s_ZRB18AR61E106ME01L; VAL4: Murata; FNLEADFREETHET1GT2GMCTH1: N_N_N; VAL3: GCM188R91H223KA37D; CAPACITANCETOLE: M; OUMECLASSIFICATION: セラミックコンデンサ; OUMEMAKERKATAMEI: ZRB18AR61E106ME01L; INSTANCENAME: INS658183
C6 = C: UPDATETIME: 17:22:43; UPDATEUSER: sptcae13; SAVECOUNT: 1; ORIGINALSYMBOLORIGIN: (0,0); QUADMODEL: CON_10U; FUNCN: C_C; NOMINALCAPACITA: 10u; RATEDVOLTAGE: 25; CDMASTERCADCELG: KC0167; MAKER: TDK; OUMEMAKER: MRT 村田製作所; ADSMODELNAME: s_ZRB18AR61E106ME01L; VAL4: Murata; FNLEADFREETHET1GT2GMCTH1: N_N_N; VAL3: GCM188R91H223KA37D; CAPACITANCETOLE: M; OUMECLASSIFICATION: セラミックコンデンサ; OUMEMAKERKATAMEI: ZRB18AR61E106ME01L; INSTANCENAME: INS658285
C7 = C: UPDATETIME: 17:22:43; UPDATEUSER: sptcae13; SAVECOUNT: 1; ORIGINALSYMBOLORIGIN: (0,0); QUADMODEL: CON_10U; FUNCN: C_C; NOMINALCAPACITA: 10u; RATEDVOLTAGE: 25; CDMASTERCADCELG: KC0167; MAKER: TDK; OUMEMAKER: MRT 村田製作所; ADSMODELNAME: s_ZRB18AR61E106ME01L; VAL4: Murata; FNLEADFREETHET1GT2GMCTH1: N_N_N; VAL3: GCM188R91H223KA37D; CAPACITANCETOLE: M; OUMECLASSIFICATION: セラミックコンデンサ; OUMEMAKERKATAMEI: ZRB18AR61E106ME01L; INSTANCENAME: INS658387
C8 = C: UPDATETIME: 17:22:43; UPDATEUSER: sptcae13; SAVECOUNT: 1; ORIGINALSYMBOLORIGIN: (0,0); QUADMODEL: CON_10U; FUNCN: C_C; NOMINALCAPACITA: 10u; RATEDVOLTAGE: 25; CDMASTERCADCELG: KC0167; MAKER: TDK; OUMEMAKER: MRT 村田製作所; ADSMODELNAME: s_ZRB18AR61E106ME01L; VAL4: Murata; FNLEADFREETHET1GT2GMCTH1: N_N_N; VAL3: GCM188R91H223KA37D; CAPACITANCETOLE: M; OUMECLASSIFICATION: セラミックコンデンサ; OUMEMAKERKATAMEI: ZRB18AR61E106ME01L; INSTANCENAME: INS658489
C15 = C: UPDATETIME: 17:22:43; UPDATEUSER: sptcae13; SAVECOUNT: 1; ORIGINALSYMBOLORIGIN: (0,0); FUNCN: C_C; VAL4: Murata; VAL3: GCM155R71H471KA37J; CDBNAME: C0805K_2; INSTANCENAME: cmp141
C16 = C: UPDATETIME: 17:22:43; UPDATEUSER: sptcae13; SAVECOUNT: 1; ORIGINALSYMBOLORIGIN: (0,0); FUNCN: C_C; VAL4: Murata; VAL3: GCM188R71H104KA57J; CDBNAME: C0805K_3; INSTANCENAME: cmp152
C17 = C: UPDATETIME: 17:22:43; UPDATEUSER: sptcae13; SAVECOUNT: 1; ORIGINALSYMBOLORIGIN: (0,0); QUADMODEL: CON_10U; FUNCN: C_C; NOMINALCAPACITA: 10u; RATEDVOLTAGE: 25; CDMASTERCADCELG: KC0167; MAKER: TDK; OUMEMAKER: MRT 村田製作所; ADSMODELNAME: s_ZRB18AR61E106ME01L; VAL4: Murata; FNLEADFREETHET1GT2GMCTH1: N_N_N; VAL3: GCM188R91H223KA37D; CAPACITANCETOLE: M; OUMECLASSIFICATION: セラミックコンデンサ; OUMEMAKERKATAMEI: ZRB18AR61E106ME01L; INSTANCENAME: INS658591
CN1 = CON2: SAVECOUNT: 1; UPDATEUSER: sptcae13; UPDATETIME: 09:49:24; OriginalSymbolOrigin: (0,0); FUNCN: CON2_CON2; VAL4: Phoenix; VAL2: 500V/32A; INSTANCENAME: INS451962
CN2 = CON10A: SAVECOUNT: 1; UPDATEUSER: sptcae13; UPDATETIME: 09:49:24; OriginalSymbolOrigin: (0,0); FUNCN: CON10A_CON10A; VAL4: Samtec; INSTANCENAME: INS465841
CN4 = CON6: SAVECOUNT: 1; UPDATEUSER: sptcae13; UPDATETIME: 09:49:24; OriginalSymbolOrigin: (0,0); FUNCN: CON6_CON6; VAL4: Harwin; INSTANCENAME: INS655764
D2 = DIODE_0: SAVECOUNT: 1; UPDATEUSER: sptcae13; UPDATETIME: 09:49:24; OriginalSymbolOrigin: (0,0); FUNCN: DIODE_0_DIODE_0; INSTANCENAME: INS572955
D3 = DIODE_0: SAVECOUNT: 1; UPDATEUSER: sptcae13; UPDATETIME: 09:49:24; OriginalSymbolOrigin: (0,0); FUNCN: DIODE_0_DIODE_0; INSTANCENAME: INS573569
IC2 = TB9005FNG_1: SAVEAREA0: -26622,-27385,86055,19754; UPDATETIME: 09:48:39; UPDATEUSER: sptcae13; TIME: 17:22:42; SAVECOUNT: 3; ORIGINALSYMBOLORIGIN: (-5080,5080); FUNCN: TB9005FNG_1_TB9005FNG_1; VAL1: LINEAR IC; INSTANCENAME: INS622199
LED1 = LED_2: SAVECOUNT: 1; UPDATEUSER: sptcae13; UPDATETIME: 09:49:24; OriginalSymbolOrigin: (0,0); FUNCN: LED_2_LED_2; VAL4: Rohm; INSTANCENAME: INS453112
LED2 = LED_2: SAVECOUNT: 1; UPDATEUSER: sptcae13; UPDATETIME: 09:49:24; OriginalSymbolOrigin: (0,0); FUNCN: LED_2_LED_2; VAL4: Rohm; INSTANCENAME: INS496113
LED3 = LED_2: SAVECOUNT: 1; UPDATEUSER: sptcae13; UPDATETIME: 09:49:24; OriginalSymbolOrigin: (0,0); FUNCN: LED_2_LED_2; VAL4: Rohm; INSTANCENAME: INS496225
Q11 = ZVP0545_TO_0: SAVECOUNT: 1; UPDATEUSER: sptcae13; UPDATETIME: 09:49:23; OriginalSymbolOrigin: (0,5080); FUNCN: ZVP0545_TO_0_ZVP0545_TO_0; INSTANCENAME: INS493920
Q12 = ZVP0545_TO_0: SAVECOUNT: 1; UPDATEUSER: sptcae13; UPDATETIME: 09:49:23; OriginalSymbolOrigin: (0,5080); FUNCN: ZVP0545_TO_0_ZVP0545_TO_0; INSTANCENAME: INS494083
Q13 = TRP: SAVEAREA0: -5466,-244,29263,20886; UPDATETIME: 17:22:43; UPDATEUSER: sptcae13; SAVECOUNT: 1; ORIGINALSYMBOLORIGIN: (0,0); FUNCN: TRP_TRP; INSTANCENAME: cmp138
R1 = R: UPDATETIME: 17:22:43; UPDATEUSER: sptcae13; SAVECOUNT: 1; ORIGINALSYMBOLORIGIN: (0,0); QUADMODEL: RES_1M; FUNCN: R_R; CDMASTERCADCELG: KC0020; MAKER: KOA; RESISTANCETOLER: J; OUMEMAKER: SSM 進工業; POWERRATING: 500m; MOUNTINGFORMSMD: SMD; NOMINALRESISTAN: 1m; ADSMODELNAME: s_RL1632H_R001_JN; FNLEADFREETHET1GT2GMCTH1: N_N_N; VAL3: RK73Z1JTTD; OUMECLASSIFICATION: 表面実装用固定抵抗器; OUMEMAKERKATAMEI: RL1632H-R001-JN; CHIPSIZE: 3216; INSTANCENAME: INS575096
R2 = R: UPDATETIME: 17:22:43; UPDATEUSER: sptcae13; SAVECOUNT: 1; ORIGINALSYMBOLORIGIN: (0,0); QUADMODEL: RES_1M; FUNCN: R_R; CDMASTERCADCELG: KC0020; MAKER: KOA; RESISTANCETOLER: J; OUMEMAKER: SSM 進工業; POWERRATING: 500m; MOUNTINGFORMSMD: SMD; NOMINALRESISTAN: 1m; ADSMODELNAME: s_RL1632H_R001_JN; FNLEADFREETHET1GT2GMCTH1: N_N_N; VAL3: RK73H1JTTD1001F; VAL2: 125mW; OUMECLASSIFICATION: 表面実装用固定抵抗器; OUMEMAKERKATAMEI: RL1632H-R001-JN; CHIPSIZE: 3216; INSTANCENAME: INS454341
R3 = R: UPDATETIME: 17:22:43; UPDATEUSER: sptcae13; SAVECOUNT: 1; ORIGINALSYMBOLORIGIN: (0,0); QUADMODEL: RES_1M; FUNCN: R_R; CDMASTERCADCELG: KC0020; MAKER: KOA; RESISTANCETOLER: J; OUMEMAKER: SSM 進工業; POWERRATING: 500m; MOUNTINGFORMSMD: SMD; NOMINALRESISTAN: 1m; ADSMODELNAME: s_RL1632H_R001_JN; FNLEADFREETHET1GT2GMCTH1: N_N_N; VAL3: RK73B1JTTD103J; VAL2: 100mW; OUMECLASSIFICATION: 表面実装用固定抵抗器; OUMEMAKERKATAMEI: RL1632H-R001-JN; CHIPSIZE: 3216; INSTANCENAME: INS486568
R4 = R: UPDATETIME: 17:22:43; UPDATEUSER: sptcae13; SAVECOUNT: 1; ORIGINALSYMBOLORIGIN: (0,0); QUADMODEL: RES_1M; FUNCN: R_R; CDMASTERCADCELG: KC0020; MAKER: KOA; RESISTANCETOLER: J; OUMEMAKER: SSM 進工業; POWERRATING: 500m; MOUNTINGFORMSMD: SMD; NOMINALRESISTAN: 1m; ADSMODELNAME: s_RL1632H_R001_JN; FNLEADFREETHET1GT2GMCTH1: N_N_N; VAL3: RK73H1JTTD2201F; VAL2: 100mW; OUMECLASSIFICATION: 表面実装用固定抵抗器; OUMEMAKERKATAMEI: RL1632H-R001-JN; CHIPSIZE: 3216; INSTANCENAME: INS471567
R5 = R: UPDATETIME: 17:22:43; UPDATEUSER: sptcae13; SAVECOUNT: 1; ORIGINALSYMBOLORIGIN: (0,0); QUADMODEL: RES_1M; FUNCN: R_R; CDMASTERCADCELG: KC0020; MAKER: KOA; RESISTANCETOLER: J; OUMEMAKER: SSM 進工業; POWERRATING: 500m; MOUNTINGFORMSMD: SMD; NOMINALRESISTAN: 1m; ADSMODELNAME: s_RL1632H_R001_JN; FNLEADFREETHET1GT2GMCTH1: N_N_N; VAL3: RK73B1JTTD103J; VAL2: 100mW; OUMECLASSIFICATION: 表面実装用固定抵抗器; OUMEMAKERKATAMEI: RL1632H-R001-JN; CHIPSIZE: 3216; INSTANCENAME: INS487189
R6 = R: UPDATETIME: 17:22:43; UPDATEUSER: sptcae13; SAVECOUNT: 1; ORIGINALSYMBOLORIGIN: (0,0); QUADMODEL: RES_1M; FUNCN: R_R; CDMASTERCADCELG: KC0020; MAKER: KOA; RESISTANCETOLER: J; OUMEMAKER: SSM 進工業; POWERRATING: 500m; MOUNTINGFORMSMD: SMD; NOMINALRESISTAN: 1m; ADSMODELNAME: s_RL1632H_R001_JN; FNLEADFREETHET1GT2GMCTH1: N_N_N; VAL3: RK73H1JTTD2201F; VAL2: 100mW; OUMECLASSIFICATION: 表面実装用固定抵抗器; OUMEMAKERKATAMEI: RL1632H-R001-JN; CHIPSIZE: 3216; INSTANCENAME: INS470310
R7 = R: UPDATETIME: 17:22:43; UPDATEUSER: sptcae13; SAVECOUNT: 1; ORIGINALSYMBOLORIGIN: (0,0); QUADMODEL: RES_1M; FUNCN: R_R; CDMASTERCADCELG: KC0020; MAKER: KOA; RESISTANCETOLER: J; OUMEMAKER: SSM 進工業; POWERRATING: 500m; MOUNTINGFORMSMD: SMD; NOMINALRESISTAN: 1m; ADSMODELNAME: s_RL1632H_R001_JN; FNLEADFREETHET1GT2GMCTH1: N_N_N; VAL3: RK73B1JTTD103J; VAL2: 100mW; OUMECLASSIFICATION: 表面実装用固定抵抗器; OUMEMAKERKATAMEI: RL1632H-R001-JN; CHIPSIZE: 3216; INSTANCENAME: INS515728
R8 = R: UPDATETIME: 17:22:43; UPDATEUSER: sptcae13; SAVECOUNT: 1; ORIGINALSYMBOLORIGIN: (0,0); QUADMODEL: RES_1M; FUNCN: R_R; CDMASTERCADCELG: KC0020; MAKER: KOA; RESISTANCETOLER: J; OUMEMAKER: SSM 進工業; POWERRATING: 500m; MOUNTINGFORMSMD: SMD; NOMINALRESISTAN: 1m; ADSMODELNAME: s_RL1632H_R001_JN; FNLEADFREETHET1GT2GMCTH1: N_N_N; VAL3: RK73B1JTTD103J; VAL2: 100mW; OUMECLASSIFICATION: 表面実装用固定抵抗器; OUMEMAKERKATAMEI: RL1632H-R001-JN; CHIPSIZE: 3216; INSTANCENAME: INS593225
R9 = R: UPDATETIME: 17:22:43; UPDATEUSER: sptcae13; SAVECOUNT: 1; ORIGINALSYMBOLORIGIN: (0,0); QUADMODEL: RES_1M; FUNCN: R_R; CDMASTERCADCELG: KC0020; MAKER: KOA; RESISTANCETOLER: J; OUMEMAKER: SSM 進工業; POWERRATING: 500m; MOUNTINGFORMSMD: SMD; NOMINALRESISTAN: 1m; ADSMODELNAME: s_RL1632H_R001_JN; FNLEADFREETHET1GT2GMCTH1: N_N_N; VAL3: RK73B1JTTD103J; VAL2: 100mW; OUMECLASSIFICATION: 表面実装用固定抵抗器; OUMEMAKERKATAMEI: RL1632H-R001-JN; CHIPSIZE: 3216; INSTANCENAME: INS593358
R10 = R: UPDATETIME: 17:22:43; UPDATEUSER: sptcae13; SAVECOUNT: 1; ORIGINALSYMBOLORIGIN: (0,0); QUADMODEL: RES_1M; FUNCN: R_R; CDMASTERCADCELG: KC0020; MAKER: KOA; RESISTANCETOLER: J; OUMEMAKER: SSM 進工業; POWERRATING: 500m; MOUNTINGFORMSMD: SMD; NOMINALRESISTAN: 1m; ADSMODELNAME: s_RL1632H_R001_JN; FNLEADFREETHET1GT2GMCTH1: N_N_N; VAL3: RK73B1JTTD103J; VAL2: 100mW; OUMECLASSIFICATION: 表面実装用固定抵抗器; OUMEMAKERKATAMEI: RL1632H-R001-JN; CHIPSIZE: 3216; INSTANCENAME: INS593492
R11 = R: UPDATETIME: 17:22:43; UPDATEUSER: sptcae13; SAVECOUNT: 1; ORIGINALSYMBOLORIGIN: (0,0); QUADMODEL: RES_1M; FUNCN: R_R; CDMASTERCADCELG: KC0020; MAKER: KOA; RESISTANCETOLER: J; OUMEMAKER: SSM 進工業; POWERRATING: 500m; MOUNTINGFORMSMD: SMD; NOMINALRESISTAN: 1m; ADSMODELNAME: s_RL1632H_R001_JN; FNLEADFREETHET1GT2GMCTH1: N_N_N; VAL3: RK73B1JTTD103J; VAL2: 100mW; OUMECLASSIFICATION: 表面実装用固定抵抗器; OUMEMAKERKATAMEI: RL1632H-R001-JN; CHIPSIZE: 3216; INSTANCENAME: INS593627
R12 = R: UPDATETIME: 17:22:43; UPDATEUSER: sptcae13; SAVECOUNT: 1; ORIGINALSYMBOLORIGIN: (0,0); QUADMODEL: RES_1M; FUNCN: R_R; CDMASTERCADCELG: KC0020; MAKER: KOA; RESISTANCETOLER: J; OUMEMAKER: SSM 進工業; POWERRATING: 500m; MOUNTINGFORMSMD: SMD; NOMINALRESISTAN: 1m; ADSMODELNAME: s_RL1632H_R001_JN; FNLEADFREETHET1GT2GMCTH1: N_N_N; VAL3: RK73B1JTTD103J; VAL2: 100mW; OUMECLASSIFICATION: 表面実装用固定抵抗器; OUMEMAKERKATAMEI: RL1632H-R001-JN; CHIPSIZE: 3216; INSTANCENAME: INS561051
R13 = R: UPDATETIME: 17:22:43; UPDATEUSER: sptcae13; SAVECOUNT: 1; ORIGINALSYMBOLORIGIN: (0,0); QUADMODEL: RES_1M; FUNCN: R_R; CDMASTERCADCELG: KC0020; MAKER: KOA; RESISTANCETOLER: J; OUMEMAKER: SSM 進工業; POWERRATING: 500m; MOUNTINGFORMSMD: SMD; NOMINALRESISTAN: 1m; ADSMODELNAME: s_RL1632H_R001_JN; FNLEADFREETHET1GT2GMCTH1: N_N_N; VAL3: RK73B1JTTD102J; VAL2: 125mW; OUMECLASSIFICATION: 表面実装用固定抵抗器; OUMEMAKERKATAMEI: RL1632H-R001-JN; CHIPSIZE: 3216; INSTANCENAME: INS467908
R14 = R: UPDATETIME: 17:22:43; UPDATEUSER: sptcae13; SAVECOUNT: 1; ORIGINALSYMBOLORIGIN: (0,0); QUADMODEL: RES_1M; FUNCN: R_R; CDMASTERCADCELG: KC0020; MAKER: KOA; RESISTANCETOLER: J; OUMEMAKER: SSM 進工業; POWERRATING: 500m; MOUNTINGFORMSMD: SMD; NOMINALRESISTAN: 1m; ADSMODELNAME: s_RL1632H_R001_JN; FNLEADFREETHET1GT2GMCTH1: N_N_N; VAL3: RK73B1JTTD513J; VAL2: 100mW; OUMECLASSIFICATION: 表面実装用固定抵抗器; OUMEMAKERKATAMEI: RL1632H-R001-JN; CHIPSIZE: 3216; INSTANCENAME: INS467930
R15 = R: UPDATETIME: 17:22:43; UPDATEUSER: sptcae13; SAVECOUNT: 1; ORIGINALSYMBOLORIGIN: (0,0); QUADMODEL: RES_1M; FUNCN: R_R; CDMASTERCADCELG: KC0020; MAKER: KOA; RESISTANCETOLER: J; OUMEMAKER: SSM 進工業; POWERRATING: 500m; MOUNTINGFORMSMD: SMD; NOMINALRESISTAN: 1m; ADSMODELNAME: s_RL1632H_R001_JN; FNLEADFREETHET1GT2GMCTH1: N_N_N; VAL3: RK73B1JTTD134J; VAL2: 100mW; OUMECLASSIFICATION: 表面実装用固定抵抗器; OUMEMAKERKATAMEI: RL1632H-R001-JN; CHIPSIZE: 3216; INSTANCENAME: INS467952
R16 = R: UPDATETIME: 17:22:43; UPDATEUSER: sptcae13; SAVECOUNT: 1; ORIGINALSYMBOLORIGIN: (0,0); QUADMODEL: RES_1M; FUNCN: R_R; CDMASTERCADCELG: KC0020; MAKER: KOA; RESISTANCETOLER: J; OUMEMAKER: SSM 進工業; POWERRATING: 500m; MOUNTINGFORMSMD: SMD; NOMINALRESISTAN: 1m; ADSMODELNAME: s_RL1632H_R001_JN; FNLEADFREETHET1GT2GMCTH1: N_N_N; VAL3: RK73B1JTTD274J; VAL2: 100mW; OUMECLASSIFICATION: 表面実装用固定抵抗器; OUMEMAKERKATAMEI: RL1632H-R001-JN; CHIPSIZE: 3216; INSTANCENAME: INS467974
R34 = R: UPDATETIME: 17:22:43; UPDATEUSER: sptcae13; SAVECOUNT: 1; ORIGINALSYMBOLORIGIN: (0,0); FUNCN: R_R; VAL4: Panasonic; VAL3: ERJ8BQFR47V; VAL2: 0.5W; CDBNAME: R1206; INSTANCENAME: cmp140
R35 = R: UPDATETIME: 17:22:43; UPDATEUSER: sptcae13; SAVECOUNT: 1; ORIGINALSYMBOLORIGIN: (0,0); QUADMODEL: RES_1M; FUNCN: R_R; CDMASTERCADCELG: KC0020; MAKER: KOA; RESISTANCETOLER: J; OUMEMAKER: SSM 進工業; POWERRATING: 500m; MOUNTINGFORMSMD: SMD; NOMINALRESISTAN: 1m; ADSMODELNAME: s_RL1632H_R001_JN; FNLEADFREETHET1GT2GMCTH1: N_N_N; VAL3: RK73Z1JTTD; OUMECLASSIFICATION: 表面実装用固定抵抗器; OUMEMAKERKATAMEI: RL1632H-R001-JN; CHIPSIZE: 3216; INSTANCENAME: INS628941
R36 = R: UPDATETIME: 17:22:43; UPDATEUSER: sptcae13; SAVECOUNT: 1; ORIGINALSYMBOLORIGIN: (0,0); QUADMODEL: RES_1M; FUNCN: R_R; CDMASTERCADCELG: KC0020; MAKER: KOA; RESISTANCETOLER: J; OUMEMAKER: SSM 進工業; POWERRATING: 500m; MOUNTINGFORMSMD: SMD; NOMINALRESISTAN: 1m; ADSMODELNAME: s_RL1632H_R001_JN; FNLEADFREETHET1GT2GMCTH1: N_N_N; VAL3: RK73Z1JTTD; OUMECLASSIFICATION: 表面実装用固定抵抗器; OUMEMAKERKATAMEI: RL1632H-R001-JN; CHIPSIZE: 3216; INSTANCENAME: INS628993
R37 = R: UPDATETIME: 17:22:43; UPDATEUSER: sptcae13; SAVECOUNT: 1; ORIGINALSYMBOLORIGIN: (0,0); QUADMODEL: RES_1M; FUNCN: R_R; CDMASTERCADCELG: KC0020; MAKER: KOA; RESISTANCETOLER: J; OUMEMAKER: SSM 進工業; POWERRATING: 500m; MOUNTINGFORMSMD: SMD; NOMINALRESISTAN: 1m; ADSMODELNAME: s_RL1632H_R001_JN; FNLEADFREETHET1GT2GMCTH1: N_N_N; VAL3: RK73Z1JTTD; OUMECLASSIFICATION: 表面実装用固定抵抗器; OUMEMAKERKATAMEI: RL1632H-R001-JN; CHIPSIZE: 3216; INSTANCENAME: INS629194
R38 = R: UPDATETIME: 17:22:43; UPDATEUSER: sptcae13; SAVECOUNT: 1; ORIGINALSYMBOLORIGIN: (0,0); QUADMODEL: RES_1M; FUNCN: R_R; CDMASTERCADCELG: KC0020; MAKER: KOA; RESISTANCETOLER: J; OUMEMAKER: SSM 進工業; POWERRATING: 500m; MOUNTINGFORMSMD: SMD; NOMINALRESISTAN: 1m; ADSMODELNAME: s_RL1632H_R001_JN; FNLEADFREETHET1GT2GMCTH1: N_N_N; VAL3: RK73Z1JTTD; OUMECLASSIFICATION: 表面実装用固定抵抗器; OUMEMAKERKATAMEI: RL1632H-R001-JN; CHIPSIZE: 3216; INSTANCENAME: INS629216
R39 = R: UPDATETIME: 17:22:43; UPDATEUSER: sptcae13; SAVECOUNT: 1; ORIGINALSYMBOLORIGIN: (0,0); QUADMODEL: RES_1M; FUNCN: R_R; CDMASTERCADCELG: KC0020; MAKER: KOA; RESISTANCETOLER: J; OUMEMAKER: SSM 進工業; POWERRATING: 500m; MOUNTINGFORMSMD: SMD; NOMINALRESISTAN: 1m; ADSMODELNAME: s_RL1632H_R001_JN; FNLEADFREETHET1GT2GMCTH1: N_N_N; VAL3: RK73Z1JTTD; OUMECLASSIFICATION: 表面実装用固定抵抗器; OUMEMAKERKATAMEI: RL1632H-R001-JN; CHIPSIZE: 3216; INSTANCENAME: INS634861
R40 = R_0: SAVECOUNT: 1; UPDATEUSER: sptcae13; UPDATETIME: 09:49:24; ORIGINALSYMBOLORIGIN: (0,0); QUADMODEL: RES_1M; FUNCN: R_0_R_0; CDMASTERCADCELG: KC0020; MAKER: KOA; RESISTANCETOLER: J; OUMEMAKER: SSM 進工業; POWERRATING: 500m; MOUNTINGFORMSMD: SMD; NOMINALRESISTAN: 1m; ADSMODELNAME: s_RL1632H_R001_JN; FNLEADFREETHET1GT2GMCTH1: N_N_N; VAL3: RK73B1JTTD331J; VAL2: 125mW; OUMECLASSIFICATION: 表面実装用固定抵抗器; OUMEMAKERKATAMEI: RL1632H-R001-JN; CHIPSIZE: 3216; INSTANCENAME: INS642505
R41 = R_0: SAVECOUNT: 1; UPDATEUSER: sptcae13; UPDATETIME: 09:49:24; ORIGINALSYMBOLORIGIN: (0,0); QUADMODEL: RES_1M; FUNCN: R_0_R_0; CDMASTERCADCELG: KC0020; MAKER: KOA; RESISTANCETOLER: J; OUMEMAKER: SSM 進工業; POWERRATING: 500m; MOUNTINGFORMSMD: SMD; NOMINALRESISTAN: 1m; ADSMODELNAME: s_RL1632H_R001_JN; FNLEADFREETHET1GT2GMCTH1: N_N_N; VAL3: RK73B1JTTD331J; VAL2: 125mW; OUMECLASSIFICATION: 表面実装用固定抵抗器; OUMEMAKERKATAMEI: RL1632H-R001-JN; CHIPSIZE: 3216; INSTANCENAME: INS642429
R42 = R_0: SAVECOUNT: 1; UPDATEUSER: sptcae13; UPDATETIME: 09:49:24; ORIGINALSYMBOLORIGIN: (0,0); QUADMODEL: RES_1M; FUNCN: R_0_R_0; CDMASTERCADCELG: KC0020; MAKER: KOA; RESISTANCETOLER: J; OUMEMAKER: SSM 進工業; POWERRATING: 500m; MOUNTINGFORMSMD: SMD; NOMINALRESISTAN: 1m; ADSMODELNAME: s_RL1632H_R001_JN; FNLEADFREETHET1GT2GMCTH1: N_N_N; VAL3: RK73B1JTTD331J; VAL2: 125mW; OUMECLASSIFICATION: 表面実装用固定抵抗器; OUMEMAKERKATAMEI: RL1632H-R001-JN; CHIPSIZE: 3216; INSTANCENAME: INS642303
R43 = R_0: SAVECOUNT: 1; UPDATEUSER: sptcae13; UPDATETIME: 09:49:24; ORIGINALSYMBOLORIGIN: (0,0); QUADMODEL: RES_1M; FUNCN: R_0_R_0; CDMASTERCADCELG: KC0020; MAKER: KOA; RESISTANCETOLER: J; OUMEMAKER: SSM 進工業; POWERRATING: 500m; MOUNTINGFORMSMD: SMD; NOMINALRESISTAN: 1m; ADSMODELNAME: s_RL1632H_R001_JN; FNLEADFREETHET1GT2GMCTH1: N_N_N; VAL3: RK73B1JTTD331J; VAL2: 125mW; OUMECLASSIFICATION: 表面実装用固定抵抗器; OUMEMAKERKATAMEI: RL1632H-R001-JN; CHIPSIZE: 3216; INSTANCENAME: INS642261
R44 = R_0: SAVECOUNT: 1; UPDATEUSER: sptcae13; UPDATETIME: 09:49:24; ORIGINALSYMBOLORIGIN: (0,0); QUADMODEL: RES_1M; FUNCN: R_0_R_0; CDMASTERCADCELG: KC0020; MAKER: KOA; RESISTANCETOLER: J; OUMEMAKER: SSM 進工業; POWERRATING: 500m; MOUNTINGFORMSMD: SMD; NOMINALRESISTAN: 1m; ADSMODELNAME: s_RL1632H_R001_JN; FNLEADFREETHET1GT2GMCTH1: N_N_N; VAL3: RK73B1JTTD331J; VAL2: 125mW; OUMECLASSIFICATION: 表面実装用固定抵抗器; OUMEMAKERKATAMEI: RL1632H-R001-JN; CHIPSIZE: 3216; INSTANCENAME: INS642387
R45 = R_0: SAVECOUNT: 1; UPDATEUSER: sptcae13; UPDATETIME: 09:49:24; ORIGINALSYMBOLORIGIN: (0,0); QUADMODEL: RES_1M; FUNCN: R_0_R_0; CDMASTERCADCELG: KC0020; MAKER: KOA; RESISTANCETOLER: J; OUMEMAKER: SSM 進工業; POWERRATING: 500m; MOUNTINGFORMSMD: SMD; NOMINALRESISTAN: 1m; ADSMODELNAME: s_RL1632H_R001_JN; FNLEADFREETHET1GT2GMCTH1: N_N_N; VAL3: RK73B1JTTD331J; VAL2: 125mW; OUMECLASSIFICATION: 表面実装用固定抵抗器; OUMEMAKERKATAMEI: RL1632H-R001-JN; CHIPSIZE: 3216; INSTANCENAME: INS642773
SW1 = 154ANS_0: SAVECOUNT: 1; UPDATEUSER: sptcae13; UPDATETIME: 09:49:24; OriginalSymbolOrigin: (-2540,0); FUNCN: 154ANS_0_154ANS_0; VAL4: NKK; VAL2: 28VDC/0.4VA; INSTANCENAME: INS614366
SW2 = 154ANS_0: SAVECOUNT: 1; UPDATEUSER: sptcae13; UPDATETIME: 09:49:24; OriginalSymbolOrigin: (-2540,0); FUNCN: 154ANS_0_154ANS_0; VAL4: NKK; VAL2: 28VDC/0.4VA; INSTANCENAME: INS473874
SW3 = 154ANS_0: SAVECOUNT: 1; UPDATEUSER: sptcae13; UPDATETIME: 09:49:24; OriginalSymbolOrigin: (-2540,0); FUNCN: 154ANS_0_154ANS_0; VAL4: NKK; VAL2: 28VDC/0.4VA; INSTANCENAME: INS614843
SW4 = 154ANS_0: SAVECOUNT: 1; UPDATEUSER: sptcae13; UPDATETIME: 09:49:24; OriginalSymbolOrigin: (-2540,0); FUNCN: 154ANS_0_154ANS_0; VAL4: NKK; VAL2: 28VDC/0.4VA; INSTANCENAME: INS614962
SW5 = 154ANS_0: SAVECOUNT: 1; UPDATEUSER: sptcae13; UPDATETIME: 09:49:24; OriginalSymbolOrigin: (-2540,0); FUNCN: 154ANS_0_154ANS_0; VAL4: NKK; VAL2: 28VDC/0.4VA; INSTANCENAME: INS615081
SW6 = 154ANS_0: SAVECOUNT: 1; UPDATEUSER: sptcae13; UPDATETIME: 09:49:24; OriginalSymbolOrigin: (-2540,0); FUNCN: 154ANS_0_154ANS_0; VAL4: NKK; VAL2: 28VDC/0.4VA; INSTANCENAME: INS615857
SW7 = 154ANS_2: SAVECOUNT: 1; UPDATEUSER: sptcae13; UPDATETIME: 09:49:24; OriginalSymbolOrigin: (-2540,0); FUNCN: 154ANS_2_154ANS_2; VAL4: Nidec Copal; INSTANCENAME: INS469431
U?#2 = WAKU_DEF100_1: SAVECOUNT: 1; UPDATEUSER: sptcae09; UPDATETIME: 10:40:02; PLOTTIME: HH:MM; TIME: 09:49:24; SAVEAREA0: -63393,-16950,474261,314592; ORIGINALSYMBOLORIGIN: (0,0); PAGENUMBER: 8; DESIGNED: TOSHIBA; SHTSAVECOUNT: 36; INSTANCENAME: INS636826

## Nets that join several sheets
D5V: 1 (C9.2 IC1.1), 2 (13 pins)
GND: 1 (25 pins), 2 (33 pins)
VB: 1 (27 pins), 2 (C2.2 IC2.1 R34.1)
VBAT: 1 (5 pins), 2 (C1.1 CN1.1)
DIAG1: 1 (IC1.2), 2 (CN2.4 Q11.G R3.2)
DIAG2: 1 (IC1.3), 2 (CN2.6 Q12.G R5.2)
IN1: 1 (IC1.21), 2 (C5.2 R8.2 R41.1)
IN2: 1 (IC1.22), 2 (C6.2 R9.2 R42.1)
IN3: 1 (IC1.23), 2 (C7.2 R10.2 R43.1)
IN4: 1 (IC1.24), 2 (C8.2 R11.2 R44.1)
MODE: 1 (IC1.17), 2 (C17.2 R12.2 R45.2)
NSLEEP: 1 (IC1.19), 2 (C4.2 R7.2 R40.1)
VDS: 1 (IC1.15), 2 (SW7.C)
